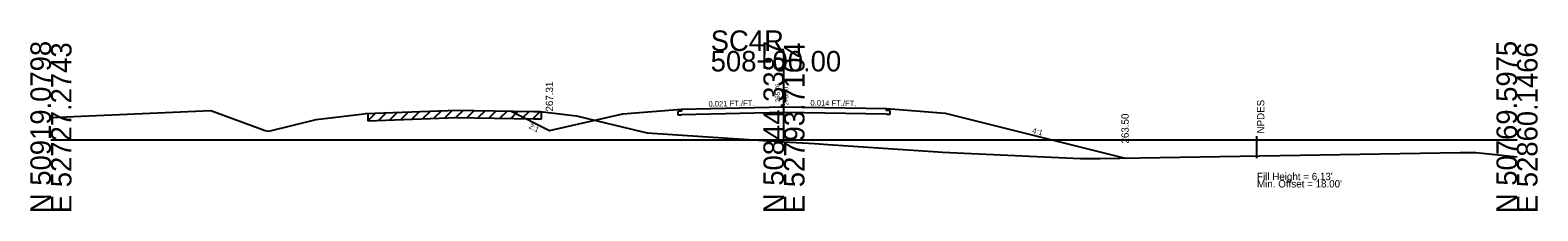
# Model space of a CAD drawing. Extents: x 7498 to 13027, y 90095 to 109625.
# Drawn here: x 8521.2 to 8726.8, y 98095.5 to 98120.2 of the extents above; entities that cross this region are included whole.
import ezdxf

# ---------------------------------------------------------------- set-up
doc = ezdxf.new("R2010")
doc.units = 0
for name, color, linetype in [('Level 10', 7, 'Continuous'), ('Level 11', 7, 'Continuous'), ('Level 12', 7, 'Continuous'), ('Level 32', 7, 'Continuous'), ('Level 33', 7, 'Continuous'), ('Level 50', 7, 'Continuous'), ('Level 55', 7, 'Continuous'), ('Level 59', 7, 'Continuous'), ('Level 6', 7, 'Continuous'), ('Level 60', 7, 'Continuous'), ('Level 61', 7, 'Continuous'), ('Level 63', 7, 'Continuous'), ('Level 7', 7, 'Continuous')]:
    doc.layers.add(name, color=color, linetype=linetype)

msp = doc.modelspace()

# ---------------------------------------------------------------- linework, layer by layer
at = {"layer": 'Level 11'}
for p, q in [((8609.99, 98109.07), (8609.49, 98109.05)), ((8609.49, 98109.05), (8609.49, 98108.57)), ((8609.49, 98108.57), (8609.99, 98108.59)), ((8609.99, 98109.37), (8609.99, 98109.07)), ((8637.99, 98109.16), (8637.99, 98109.46)), ((8638.49, 98109.15), (8637.99, 98109.16)), ((8637.99, 98108.68), (8638.49, 98108.67)), ((8638.49, 98108.67), (8638.49, 98109.15))]:
    msp.add_line(p, q, dxfattribs=at)
at = {"layer": 'Level 12'}
for p, q in [((8623.99, 98108.88), (8609.99, 98108.59)), ((8637.99, 98108.68), (8623.99, 98108.88))]:
    msp.add_line(p, q, dxfattribs=at)
at = {"layer": 'Level 55'}
msp.add_line((8688.52, 98102.66), (8688.52, 98105.66), dxfattribs=at)
at = {"layer": 'Level 59'}
for p, q in [((8609.99, 98109.37), (8623.99, 98109.66)), ((8623.99, 98109.66), (8637.99, 98109.46))]:
    msp.add_line(p, q, dxfattribs=at)
at = {"layer": 'Level 6'}
for p, q in [((8601.99, 98108.7), (8609.99, 98109.37)), ((8637.99, 98109.46), (8645.99, 98108.79))]:
    msp.add_line(p, q, dxfattribs=at)
at = {"layer": 'Level 60'}
for p, q in [((8523.99, 98108.23), (8545.79, 98109.16)), ((8545.79, 98109.16), (8553.22, 98106.46)), ((8560.17, 98107.96), (8566.3, 98108.69)), ((8566.3, 98108.69), (8566.88, 98108.77)), ((8566.88, 98108.77), (8578.2, 98109.19)), ((8578.2, 98109.19), (8579.04, 98109.21)), ((8579.04, 98109.21), (8589.88, 98109.03)), ((8589.88, 98109.03), (8590.71, 98109.03)), ((8590.71, 98109.03), (8595.26, 98108.51)), ((8595.26, 98108.51), (8595.69, 98108.45)), ((8595.69, 98108.45), (8604.75, 98106.26)), ((8553.22, 98106.46), (8553.7, 98106.35)), ((8553.7, 98106.35), (8560.17, 98107.96)), ((8604.75, 98106.26), (8605.31, 98106.12)), ((8605.31, 98106.12), (8623.99, 98104.91)), ((8623.99, 98104.91), (8628.17, 98104.65)), ((8628.17, 98104.65), (8630, 98104.55)), ((8630, 98104.55), (8645.01, 98103.52)), ((8645.01, 98103.52), (8645.62, 98103.49)), ((8645.62, 98103.49), (8664.45, 98102.64)), ((8664.45, 98102.64), (8667.09, 98102.6)), ((8667.09, 98102.6), (8716.25, 98103.45)), ((8716.25, 98103.45), (8718.44, 98103.42)), ((8718.44, 98103.42), (8723.99, 98102.83))]:
    msp.add_line(p, q, dxfattribs=at)
at = {"layer": 'Level 61'}
for p, q in [((8568.26, 98108.82), (8567.23, 98107.78)), ((8567.23, 98108.78), (8567.23, 98107.78)), ((8567.23, 98107.78), (8578.2, 98108.19)), ((8569.76, 98108.88), (8568.73, 98107.84)), ((8571.26, 98108.93), (8570.23, 98107.89)), ((8572.76, 98108.99), (8571.73, 98107.95)), ((8574.26, 98109.04), (8573.23, 98108.01)), ((8575.76, 98109.1), (8574.73, 98108.06)), ((8577.26, 98109.15), (8576.23, 98108.12)), ((8578.76, 98109.2), (8577.73, 98108.17)), ((8578.2, 98108.19), (8579.04, 98108.21)), ((8579.04, 98108.21), (8589.88, 98108.03)), ((8580.21, 98109.19), (8579.23, 98108.21)), ((8581.71, 98109.17), (8580.73, 98108.18)), ((8583.21, 98109.14), (8582.23, 98108.16)), ((8584.71, 98109.12), (8583.73, 98108.13)), ((8586.21, 98109.09), (8585.23, 98108.11)), ((8587.71, 98109.07), (8586.73, 98108.08)), ((8589.21, 98109.04), (8588.23, 98108.06)), ((8590.72, 98109.03), (8589.73, 98108.03)), ((8589.88, 98108.03), (8590.71, 98108.03)), ((8590.71, 98108.03), (8590.92, 98108)), ((8590.92, 98108), (8590.92, 98109))]:
    msp.add_line(p, q, dxfattribs=at)
at = {"layer": 'Level 63'}
for p, q in [((8623.99, 98105.16), (8623.99, 98117.31)), ((8523.99, 98105.16), (8623.99, 98105.16)), ((8623.99, 98105.16), (8723.99, 98105.16))]:
    msp.add_line(p, q, dxfattribs=at)
at = {"layer": 'Level 7'}
for p, q in [((8586.75, 98109.08), (8591.99, 98106.46)), ((8591.99, 98106.46), (8601.99, 98108.7)), ((8645.99, 98108.79), (8670.52, 98102.66))]:
    msp.add_line(p, q, dxfattribs=at)

# ---------------------------------------------------------------- texts
at = {"layer": 'Level 10'}
msp.add_text('265.76', height=0.6, rotation=90, dxfattribs=at).set_placement((8623.42, 98110.32))
at = {"layer": 'Level 32'}
for s, rotation, p in [('0.021 FT./FT.', 1.1916, (8613.7, 98109.69)), ('0.014 FT./FT.', 359.1793, (8627.59, 98109.85)), ('2:1', 333.435, (8589.09, 98106.8)), ('4:1', 345.9638, (8657.8, 98106.09))]:
    msp.add_text(s, height=0.75, rotation=rotation, dxfattribs=at).set_placement(p)
at = {"layer": 'Level 33'}
for s, p in [('267.31', (8592.49, 98109.03)), ('263.50', (8671.02, 98104.66))]:
    msp.add_text(s, height=1, rotation=90, dxfattribs=at).set_placement(p)
at = {"layer": 'Level 50'}
msp.add_text(' NPDES', height=1, rotation=90, dxfattribs=at).set_placement((8689.52, 98105.66))
for s, p in [("Fill Height = 6.13' ", (8688.52, 98099.66)), ("Min. Offset = 18.00' ", (8688.52, 98098.66))]:
    msp.add_text(s, height=1, dxfattribs=at).set_placement(p)
at = {"layer": 'Level 59'}
msp.add_text(' 270.50', height=0.6, rotation=90, dxfattribs=at).set_placement((8624.59, 98109.66))
at = {"layer": 'Level 63'}
for s, p in [('N 50919.0798', (8523.99, 98095.16)), ('E 52727.2743', (8526.79, 98095.16)), ('N 50844.3387', (8623.99, 98095.16)), ('E 52793.7104', (8626.79, 98095.16)), ('N 50769.5975', (8723.99, 98095.16)), ('E 52860.1466', (8726.79, 98095.16))]:
    msp.add_text(s, height=2.8, rotation=90, dxfattribs=at).set_placement(p)
for s, p in [('SC4R', (8613.99, 98117.31)), ('508+00.00', (8613.99, 98114.51))]:
    msp.add_text(s, height=2.8, dxfattribs=at).set_placement(p)

doc.saveas('drawing.dxf')
